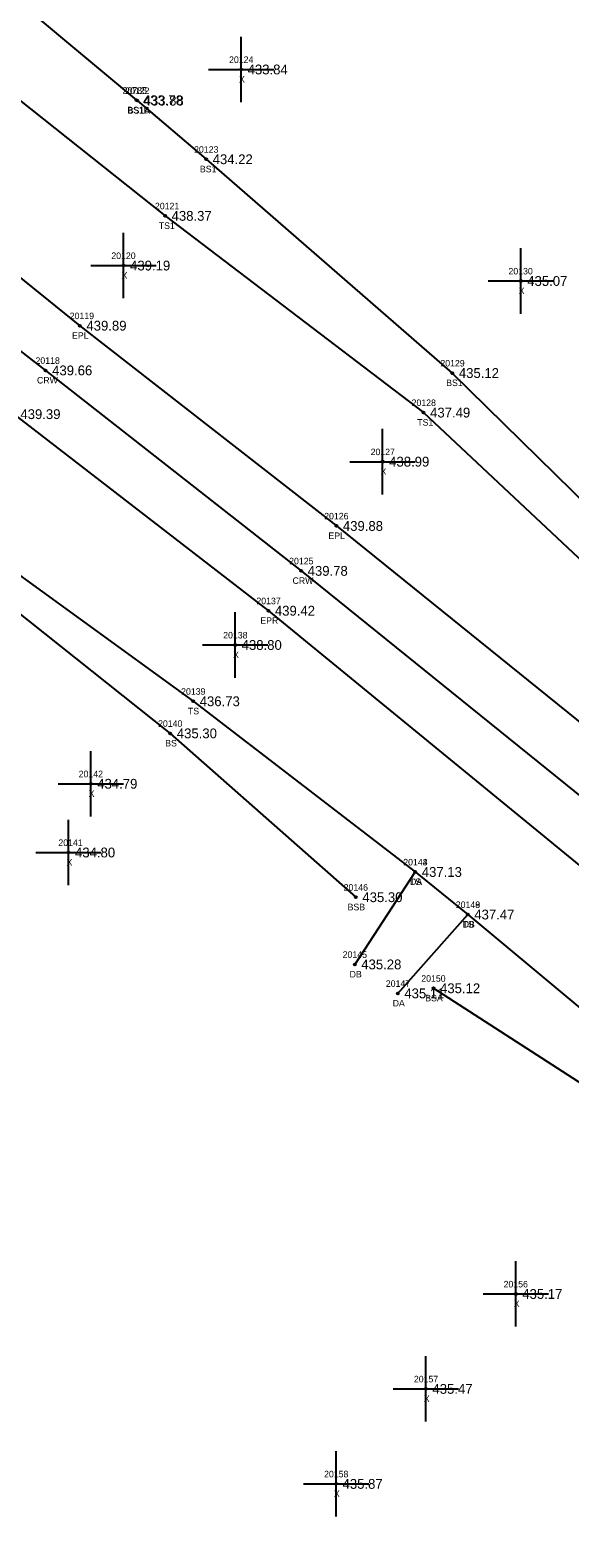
# Model space of a CAD drawing. Extents: x 1613836 to 1615109, y 777151 to 778248.
# Drawn here: x 1614247 to 1614329.5, y 777687.6 to 777918.3 of the extents above; entities that cross this region are included whole.
import ezdxf

# ---------------------------------------------------------------- set-up
doc = ezdxf.new("R2010")
doc.units = 0
for name, color, linetype in [('RD_DTM_BkLn1', 7, 'Continuous'), ('RD_DTM_BkLn2', 7, 'Continuous'), ('RD_DTM_BkLn_txCode', 7, 'Continuous'), ('RD_EX_Driveway', 7, 'Continuous'), ('RD_EX_Driveway_txCode', 7, 'Continuous'), ('RD_EX_Misc', 7, 'Continuous'), ('RD_EX_Misc_txCode', 7, 'Continuous'), ('RD_EX_Road', 7, 'Continuous'), ('RD_EX_Road_txCode', 7, 'Continuous'), ('RD_EX_TX_Driveway_ELEV', 7, 'Continuous'), ('RD_EX_TX_Misc_ELEV', 7, 'Continuous'), ('RD_EX_TX_Road_ELEV', 7, 'Continuous'), ('RD_HC_Survey_ELEV', 7, 'Continuous'), ('RD_HC_Survey_txCode', 7, 'Continuous'), ('RD_SMD_Locator', 7, 'Continuous')]:
    doc.layers.add(name, color=color, linetype=linetype)

msp = doc.modelspace()

# ---------------------------------------------------------------- linework, layer by layer
at = {"layer": 'RD_DTM_BkLn1'}
msp.add_lwpolyline([(1613865.21, 778095.86), (1613910.73, 778075.92), (1613956.18, 778054.99), (1614000.73, 778032.51), (1614044.52, 778008.68), (1614087.21, 777982.81), (1614129.12, 777955.82), (1614169.63, 777926.64), (1614209.9, 777896.76), (1614249.35, 777866.21), (1614288.43, 777835.55), (1614366.39, 777772.65), (1614443.98, 777709.72)], dxfattribs=at)
at = {"layer": 'RD_DTM_BkLn2'}
for points in [[(1613870.65, 778107.91), (1613917.36, 778089.81), (1613963.47, 778068.53), (1614008.76, 778046.32), (1614052.42, 778023.01), (1614094.96, 777996.37), (1614137.71, 777969), (1614179.06, 777940.06), (1614196.49, 777927.41), (1614202.23, 777922.93), (1614210.94, 777920.91), (1614226.4, 777922.61), (1614267.62, 777889.85), (1614307.16, 777859.76), (1614381.32, 777790.21), (1614451.43, 777721.4), (1614453.49, 777722.08), (1614455.33, 777720.48), (1614437.07, 777696.16)], [(1613860.36, 778083.39), (1613904.96, 778062.9), (1613950.73, 778042.94), (1613994.86, 778021.25), (1614038.25, 777997.65), (1614118.58, 777941.84), (1614160.54, 777914.82), (1614182.29, 777896.21), (1614189.42, 777895.9), (1614196.65, 777882.72), (1614195.5, 777875.76), (1614231.56, 777844.86), (1614271.92, 777815.6), (1614305.89, 777789.49), (1614313.92, 777782.98), (1614351.2, 777751.93), (1614424.47, 777701.24), (1614433.25, 777695.63), (1614437.07, 777696.16)], [(1614222.94, 777931.87), (1614229.64, 777933.19), (1614238.68, 777928.06), (1614263.24, 777907.54)], [(1614263.34, 777907.48), (1614273.9, 777898.51), (1614311.56, 777865.81), (1614385.12, 777793.65), (1614458.7, 777729.38), (1614464.37, 777721.53)], [(1614186.09, 777882.37), (1614189.71, 777873.35), (1614229.91, 777841.27), (1614268.42, 777810.69), (1614296.8, 777785.63)], [(1614308.68, 777771.7), (1614347.33, 777746.8), (1614414.57, 777695.15), (1614432.9, 777688.24), (1614439.87, 777687.64), (1614444.54, 777689.78)]]:
    msp.add_lwpolyline(points, dxfattribs=at)
at = {"layer": 'RD_EX_Driveway'}
for p, q in [((1614305.89, 777789.49), (1614296.63, 777775.35)), ((1614303.22, 777770.92), (1614313.92, 777782.98))]:
    msp.add_line(p, q, dxfattribs=at)
at = {"layer": 'RD_EX_Misc'}
for p, q in [((1614279.25, 777907.24), (1614279.25, 777917.24)), ((1614274.25, 777912.24), (1614284.25, 777912.24)), ((1614261.27, 777877.25), (1614261.27, 777887.25)), ((1614322.02, 777874.89), (1614322.02, 777884.89)), ((1614256.27, 777882.25), (1614266.27, 777882.25)), ((1614317.02, 777879.89), (1614327.02, 777879.89)), ((1614300.9, 777847.25), (1614300.9, 777857.25)), ((1614295.9, 777852.25), (1614305.9, 777852.25)), ((1614278.34, 777819.21), (1614278.34, 777829.21)), ((1614273.34, 777824.21), (1614283.34, 777824.21)), ((1614256.25, 777797.98), (1614256.25, 777807.98)), ((1614251.25, 777802.98), (1614261.25, 777802.98)), ((1614252.85, 777787.47), (1614252.85, 777797.47)), ((1614247.85, 777792.47), (1614257.85, 777792.47)), ((1614321.26, 777719.94), (1614321.26, 777729.94)), ((1614316.26, 777724.94), (1614326.26, 777724.94)), ((1614307.52, 777705.42), (1614307.52, 777715.42)), ((1614302.52, 777710.42), (1614312.52, 777710.42)), ((1614293.77, 777690.89), (1614293.77, 777700.89)), ((1614288.77, 777695.89), (1614298.77, 777695.89))]:
    msp.add_line(p, q, dxfattribs=at)
at = {"layer": 'RD_EX_Road'}
for points in [[(1613868.87, 778104.15), (1613915.02, 778083.82), (1613960.16, 778062.2), (1614004.58, 778040.28), (1614048.84, 778015.98), (1614091.38, 777990.08), (1614134.36, 777962.6), (1614174.73, 777933.48), (1614192.07, 777920.58), (1614215.93, 777904.23), (1614254.59, 777873.05), (1614293.82, 777842.42), (1614371.74, 777779.59), (1614449.33, 777716.3), (1614443.98, 777709.72), (1614439.38, 777704.09)], [(1613862.14, 778087.92), (1613908.12, 778068.22), (1613952.96, 778047.38), (1613997, 778025.09), (1614041.16, 778001.63), (1614124.35, 777949.06), (1614164.51, 777920.91), (1614187.11, 777904.29), (1614205.27, 777889.82), (1614244.49, 777859.52), (1614283.42, 777829.45), (1614361.06, 777765.89), (1614439.38, 777704.09)]]:
    msp.add_lwpolyline(points, dxfattribs=at)
at = {"layer": 'RD_SMD_Locator'}
for centre in [(1614279.25, 777912.24), (1614263.24, 777907.54), (1614263.34, 777907.48), (1614273.9, 777898.51), (1614267.62, 777889.85), (1614261.27, 777882.25), (1614322.02, 777879.89), (1614254.59, 777873.05), (1614249.35, 777866.21), (1614311.56, 777865.81), (1614307.16, 777859.76), (1614300.9, 777852.25), (1614293.82, 777842.42), (1614288.43, 777835.55), (1614283.42, 777829.45), (1614278.34, 777824.21), (1614271.92, 777815.6), (1614268.42, 777810.69), (1614256.25, 777802.98), (1614252.85, 777792.47), (1614305.89, 777789.49), (1614305.89, 777789.49), (1614296.8, 777785.63), (1614313.92, 777782.98), (1614313.92, 777782.98), (1614296.63, 777775.35), (1614303.22, 777770.92), (1614308.68, 777771.7), (1614321.26, 777724.94), (1614307.52, 777710.42), (1614293.77, 777695.89)]:
    msp.add_circle(centre, 0.15, dxfattribs=at)

# ---------------------------------------------------------------- texts
at = {"layer": 'RD_DTM_BkLn_txCode'}
for s, p in [('20785', (1614261.13, 777908.54)), ('20122', (1614261.51, 777908.48)), ('BS1B', (1614261.83, 777905.54)), ('BS1A', (1614261.91, 777905.48)), ('20123', (1614272.06, 777899.51)), ('BS1', (1614272.95, 777896.51)), ('20121', (1614266.07, 777890.85)), ('TS1', (1614266.66, 777887.85)), ('20129', (1614309.73, 777866.81)), ('BS1', (1614310.62, 777863.81)), ('20128', (1614305.33, 777860.76)), ('TS1', (1614306.2, 777857.76)), ('20139', (1614270.08, 777816.6)), ('TS', (1614271.12, 777813.6)), ('20140', (1614266.55, 777811.69)), ('BS', (1614267.64, 777808.69)), ('20143', (1614304.05, 777790.49)), ('20146', (1614294.94, 777786.63)), ('TS', (1614305.09, 777787.49)), ('BSB', (1614295.54, 777783.63)), ('20149', (1614312.09, 777783.98)), ('TS', (1614313.12, 777780.98)), ('20150', (1614306.81, 777772.7)), ('BSA', (1614307.42, 777769.7))]:
    msp.add_text(s, height=1, dxfattribs=at).set_placement(p)
at = {"layer": 'RD_EX_Driveway_txCode'}
for s, p in [('20144', (1614304.05, 777790.49)), ('DA', (1614305.09, 777787.49)), ('20148', (1614312.09, 777783.98)), ('DB', (1614313.14, 777780.98)), ('20145', (1614294.79, 777776.35)), ('DB', (1614295.85, 777773.35)), ('20147', (1614301.39, 777771.92)), ('DA', (1614302.43, 777768.92))]:
    msp.add_text(s, height=1, dxfattribs=at).set_placement(p)
at = {"layer": 'RD_EX_Misc_txCode'}
for s, p in [('20124', (1614277.41, 777913.24)), ('X', (1614278.93, 777910.24)), ('20120', (1614259.4, 777883.25)), ('20130', (1614320.15, 777880.89)), ('X', (1614260.96, 777880.25)), ('X', (1614321.71, 777877.89)), ('20127', (1614299.06, 777853.25)), ('X', (1614300.58, 777850.25)), ('20138', (1614276.51, 777825.21)), ('X', (1614278.03, 777822.21)), ('20142', (1614254.41, 777803.98)), ('X', (1614255.93, 777800.98)), ('20141', (1614251.3, 777793.47)), ('X', (1614252.54, 777790.47)), ('20156', (1614319.4, 777725.94)), ('X', (1614320.95, 777722.94)), ('20157', (1614305.68, 777711.42)), ('X', (1614307.2, 777708.42)), ('20158', (1614291.94, 777696.89)), ('X', (1614293.45, 777693.89))]:
    msp.add_text(s, height=1, dxfattribs=at).set_placement(p)
at = {"layer": 'RD_EX_Road_txCode'}
for s, p in [('20119', (1614253.04, 777874.05)), ('EPL', (1614253.39, 777871.05)), ('20126', (1614291.96, 777843.42)), ('EPL', (1614292.61, 777840.42)), ('20137', (1614281.59, 777830.45)), ('EPR', (1614282.19, 777827.45))]:
    msp.add_text(s, height=1, dxfattribs=at).set_placement(p)
at = {"layer": 'RD_EX_TX_Driveway_ELEV'}
for s, p in [('437.13', (1614306.89, 777788.74)), ('437.47', (1614314.92, 777782.23)), ('435.28', (1614297.63, 777774.6)), ('435.11', (1614304.22, 777770.17))]:
    msp.add_text(s, height=1.5, dxfattribs=at).set_placement(p)
at = {"layer": 'RD_EX_TX_Misc_ELEV'}
for s, p in [('433.84', (1614280.25, 777911.49)), ('433.78', (1614264.24, 777906.79)), ('433.88', (1614264.34, 777906.73)), ('434.22', (1614274.9, 777897.76)), ('438.37', (1614268.62, 777889.1)), ('439.19', (1614262.27, 777881.5)), ('435.07', (1614323.02, 777879.14)), ('435.12', (1614312.56, 777865.06)), ('437.49', (1614308.16, 777859.01)), ('438.99', (1614301.9, 777851.5)), ('438.80', (1614279.34, 777823.46)), ('436.73', (1614272.92, 777814.85)), ('435.30', (1614269.42, 777809.94)), ('434.79', (1614257.25, 777802.23)), ('434.80', (1614253.85, 777791.72)), ('437.13', (1614306.89, 777788.74)), ('435.30', (1614297.8, 777784.88)), ('437.47', (1614314.92, 777782.23)), ('435.12', (1614309.68, 777770.95)), ('435.17', (1614322.26, 777724.19)), ('435.47', (1614308.52, 777709.67)), ('435.87', (1614294.77, 777695.14))]:
    msp.add_text(s, height=1.5, dxfattribs=at).set_placement(p)
at = {"layer": 'RD_EX_TX_Road_ELEV'}
for s, p in [('439.89', (1614255.59, 777872.3)), ('439.39', (1614245.49, 777858.77)), ('439.88', (1614294.82, 777841.67)), ('439.42', (1614284.42, 777828.7))]:
    msp.add_text(s, height=1.5, dxfattribs=at).set_placement(p)
at = {"layer": 'RD_HC_Survey_ELEV'}
for s, p in [('439.66', (1614250.35, 777865.46)), ('439.78', (1614289.43, 777834.8))]:
    msp.add_text(s, height=1.5, dxfattribs=at).set_placement(p)
at = {"layer": 'RD_HC_Survey_txCode'}
for s, p in [('20118', (1614247.8, 777867.21)), ('CRW', (1614248.03, 777864.21)), ('20125', (1614286.6, 777836.55)), ('CRW', (1614287.12, 777833.55))]:
    msp.add_text(s, height=1, dxfattribs=at).set_placement(p)

doc.saveas('drawing.dxf')
